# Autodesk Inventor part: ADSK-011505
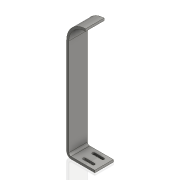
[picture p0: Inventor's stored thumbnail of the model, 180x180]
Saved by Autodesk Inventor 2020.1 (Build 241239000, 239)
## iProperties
Created: 2000-02
Part Number: ADSK-011505
Material: 1.0312 DC05
Description: FSHTPH,FS,CP,02,127,030,PLOW,END_TAB
Document SubType Name: Tôlerie
Designer: sspink
Density: 1 g/cm^3
Sheet Metal Rule: Stahlblech 1.0312 - DC05 -   6.0 mm
Appearance: Stahl
Mass: 124.286 g
Surface Area: 478.79 cm^2
Volume: 124.286 cm^3
Flat Pattern Width: 41.3404 cm
Flat Pattern Length: 5.1 cm
Flat Pattern Area: 210.836 cm^2
Sheet Metal Width: 413,404 mm
Sheet Metal Length: 51,000 mm
Sheet Metal Area: 21083,625 mm^2
Control State: 0
Checked Out: False
Master: False
Shininess: 57.0
Length Units: 11269
Angle Units: 11279
Time Units: 11290
Mass Units: 11283
Length Display Precision: 3
Angle Display Precision: 2
Compacted: True
Cutlength: 16.25
Material Desc: FLAT,S/S,0.250 X 2.00
Material_number: A084860
G_L: 51x413,4 mm
Thickness: 6,000 mm
Dimensions: 76x324x51 mm
Mass: 0,124 kg
Semi finished: Stahlblech 1.0312 - DC05 -   6.0 mm
Density: 8.03
Volumn: 130.61531183541348
Area: 479.66770697949045
PropertySet Name: Model Information
Author: sspink
Revision Number: -
Title: FSHTPH,FS,CP,02,127,030,PLOW,END_TAB
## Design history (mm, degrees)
node "Solide1"
  node "Extrusion1" dims "d10" = 51, "d11" = 0
  node "Fillet3" dims "d14" = 12 (= 2 x thickness)
  node "Fillet4" dims "d15" = 6 (= thickness)
  node "Extrusion2" dims "d22" = 25.4, "d23" = 0
sketch "Sketch1"
  geometry: L1 (0, 0)-(1.465, 0); L2 (6, 6)-(6, 273); L3 (6, 273)-(0, 273); L4 (0, 273)-(0, 0); L5 (0, 0)-(76, 0); L6 (76, 0)-(76, 6); L7 (76, 6)-(6, 6); L8 (6, 273)-(51, 273); L9 (51, 273)-(51, 324); L10 (51, 273)-(51, 324); L11 (51, 324)-(51, 318); L12 (51, 324)-(51, 318); A1 r 45 centre (51, 273) between (51, 318) and (6, 273); A2 r 51 centre (51, 273) between (51, 324) and (6, 249)
  constraints: 24 end point, 5 point on circle, 4 parallel, 4 perpendicular, 2 centre point, 2 coincident, 2 collinear, 2 point on line, 1 horizontal, 1 tangent
  dimensions: "d0" = 76 distance between parallel lines of L6 L4; "d1" = 273 distance between parallel lines of L3 L5; "d3" = 6 distance between parallel lines of L2 L4 (= thickness); "d4" = 6 distance between parallel lines of L7 L5 (= thickness); "d32" = 45 distance of L2.end L8.end
workplane "Arbeitsebene1"
workplane "Arbeitsebene2"
sketch "Sketch2"
  geometry: L1 (0, 51)-(0, 0) reference; L2 (-41, 9.5)-(-16, 9.5); L3 (-16, 9.5)-(-16, 16.5); L4 (-16, 16.5)-(-41, 16.5); L5 (-41, 16.5)-(-41, 9.5); L6 (-41, 34.5)-(-16, 34.5); L7 (-16, 34.5)-(-16, 41.5); L8 (-16, 41.5)-(-41, 41.5); L9 (-41, 41.5)-(-41, 34.5); L10 (-41, 38)-(-16, 38); L11 (-41, 13)-(-15.517, 13); L12 (-28.5, 38)-(-28.5, 13); A1 r 3.5 centre (-16, 13) between (-16, 9.5) and (-16, 16.5); A2 r 3.5 centre (-16, 38) between (-16, 34.5) and (-16, 41.5); A3 r 3.5 centre (-41, 13) between (-41, 16.5) and (-41, 9.5); A4 r 3.5 centre (-41, 38) between (-41, 41.5) and (-41, 34.5); 4 further points
  constraints: 22 end point, 8 point on circle, 5 midpoint, 5 perpendicular, 4 centre point, 4 parallel, 4 tangent, 2 equal length, 2 horizontal, 1 horizontal alignment, 1 point on line, 1 vertical alignment
  dimensions: "d16" = 7 distance between parallel lines of L4 L2; "d17" = 25 distance of L2.start L2.end; "d20" = 16 distance between parallel lines of L7 L1; "d33" = 25 distance of L12.start L12.end
node "FlatPattern"
node "Corps solides"
node "Corps surfaciques"
feature "Extrusion_mise_à_plat2" dims "d0" = 6 (derived)
other parameters: "thickness" = 6 [user parameter; used in 4 equation terms], "Thickness" = 6 (derived), "BendRadius" = 6 (= Thickness), "BendReliefWidth" = 6 (= Thickness), "BendReliefDepth" = 3 (= 0.5 x Thickness), "CornerReliefSize" = 24 (= 4 x Thickness), "SeamGap" = 0.00508, "MinimumRemnant" = 12 (= 2 x Thickness), "TransitionRadius" = 6 (= BendRadius), "TailleRayonJacobi" = 6 (= BendRadius), "TailleJeu" = 6 (= Thickness)
